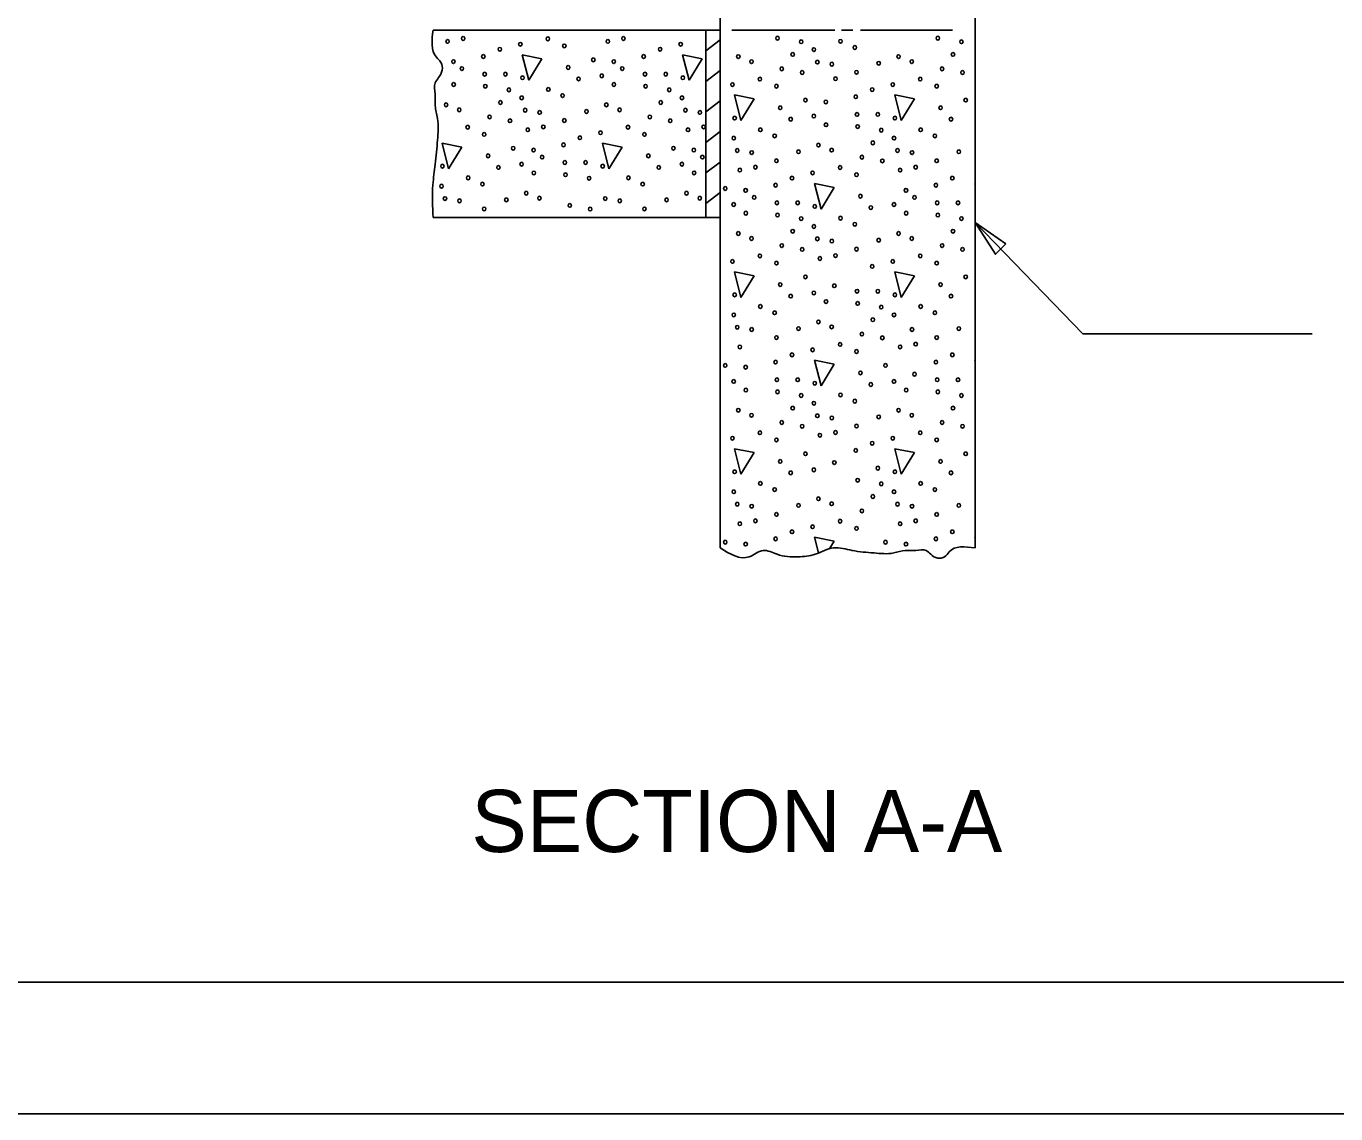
# Model space of a CAD drawing. Extents: x 0 to 34, y 0 to 22.
# Drawn here: x 9.28 to 14.256, y 0 to 4.131 of the extents above; entities that cross this region are included whole.
import ezdxf

# ---------------------------------------------------------------- set-up
doc = ezdxf.new("R2010")
doc.units = 0
for name, color, linetype in [('SH_Border', 7, 'Continuous'), ('SH_Cut_Line', 7, 'Continuous'), ('ST_Details', 7, 'Continuous'), ('ST_Text', 7, 'Continuous')]:
    doc.layers.add(name, color=color, linetype=linetype)

msp = doc.modelspace()

# ---------------------------------------------------------------- linework, layer by layer
at = {"layer": 'SH_Border'}
msp.add_lwpolyline([(2, 21.5), (33.5, 21.5), (33.5, 0.5), (2, 0.5)], close=True, dxfattribs=at)
at = {"layer": 'SH_Cut_Line'}
msp.add_lwpolyline([(0, 0), (34, 0), (34, 22), (0, 22)], close=True, dxfattribs=at)
at = {"layer": 'ST_Details'}
for p, q in [((12.8855, 2.1494), (12.8855, 5.9845)), ((11.9167, 4.294), (11.9167, 4.116)), ((11.8628, 4.116), (10.8265, 4.116)), ((11.9167, 4.116), (11.8628, 4.116)), ((11.8628, 4.1159), (11.8628, 3.4035)), ((11.9167, 3.3947), (11.9167, 4.116)), ((12.3533, 4.116), (11.962, 4.116)), ((12.4217, 4.116), (12.3782, 4.116)), ((12.8002, 4.116), (12.4497, 4.116)), ((11.1653, 4.0224), (11.1898, 3.925)), ((11.24, 4.0072), (11.1653, 4.0224)), ((11.1898, 3.925), (11.24, 4.0072)), ((11.7743, 4.0224), (11.799, 3.925)), ((11.8492, 4.0072), (11.7743, 4.0224)), ((11.799, 3.925), (11.8492, 4.0072)), ((11.9712, 3.8694), (11.9957, 3.772)), ((12.0458, 3.8542), (11.9712, 3.8694)), ((11.9957, 3.772), (12.0458, 3.8542)), ((12.5802, 3.8694), (12.6048, 3.772)), ((12.655, 3.8542), (12.5802, 3.8694)), ((12.6048, 3.772), (12.655, 3.8542)), ((10.8608, 3.6865), (10.8855, 3.5892)), ((11.4698, 3.6865), (11.4945, 3.5892)), ((11.5447, 3.6714), (11.4698, 3.6865)), ((10.8855, 3.5892), (10.9355, 3.6714)), ((11.4945, 3.5892), (11.5447, 3.6714)), ((12.2755, 3.5335), (12.3002, 3.4362)), ((12.3503, 3.5184), (12.2755, 3.5335)), ((12.3002, 3.4362), (12.3503, 3.5184)), ((10.8265, 3.4035), (11.8628, 3.4035)), ((11.8628, 3.4035), (11.9167, 3.4035)), ((11.9167, 3.3947), (11.9167, 2.1494)), ((11.9712, 3.1977), (11.9957, 3.1004)), ((12.0458, 3.1825), (11.9712, 3.1977)), ((12.5802, 3.1977), (12.6048, 3.1004)), ((12.655, 3.1825), (12.5802, 3.1977)), ((11.9957, 3.1004), (12.0458, 3.1825)), ((12.6048, 3.1004), (12.655, 3.1825)), ((12.2755, 2.8619), (12.3002, 2.7645)), ((12.3503, 2.8467), (12.2755, 2.8619)), ((12.3002, 2.7645), (12.3503, 2.8467)), ((11.9712, 2.526), (11.9957, 2.4287)), ((12.0458, 2.5109), (11.9712, 2.526)), ((11.9957, 2.4287), (12.0458, 2.5109)), ((12.5802, 2.526), (12.6048, 2.4287)), ((12.655, 2.5109), (12.5802, 2.526)), ((12.6048, 2.4287), (12.655, 2.5109)), ((12.2755, 2.1902), (12.2908, 2.1299)), ((12.3503, 2.175), (12.2755, 2.1902))]:
    msp.add_line(p, q, dxfattribs=at)
for points in [[(11.8627, 4.037), (11.9167, 4.0785)], [(11.8628, 3.921), (11.9165, 3.9625)], [(11.8628, 3.805), (11.9165, 3.8465)], [(10.9355, 3.6714), (10.8608, 3.6865)], [(11.8628, 3.6892), (11.9165, 3.7307)], [(11.8628, 3.5732), (11.9167, 3.6147)], [(12.8847, 3.5335), (12.8855, 3.5297)], [(12.8855, 3.5334), (12.8847, 3.5335)], [(11.8628, 3.4572), (11.9167, 3.4989)], [(12.8847, 2.8619), (12.8855, 2.858)], [(12.8855, 2.8617), (12.8847, 2.8619)], [(12.8847, 2.1902), (12.8855, 2.1865)], [(12.8855, 2.19), (12.8847, 2.1902)], [(12.3338, 2.1482), (12.3503, 2.175)]]:
    msp.add_lwpolyline(points, dxfattribs=at)
for centre in [(10.8814, 4.073), (10.9406, 4.084), (11.2624, 4.0827), (11.4904, 4.073), (11.5496, 4.084), (12.135, 4.0851), (12.3743, 4.0733), (12.7441, 4.0851), (11.0798, 4.0428), (11.158, 4.0618), (11.3249, 4.0555), (11.6889, 4.0428), (11.767, 4.0618), (12.1926, 4.0235), (12.2247, 4.0715), (12.2732, 4.0416), (12.4286, 4.0498), (12.8016, 4.0235), (12.8337, 4.0715), (10.9037, 3.996), (11.0174, 4.0156), (11.3397, 3.9739), (11.4351, 4.003), (11.5127, 3.996), (11.6264, 4.0156), (11.986, 4.015), (12.0361, 3.996), (12.2864, 3.9945), (12.3414, 3.9862), (12.5193, 3.9897), (12.595, 4.015), (12.6451, 3.996), (10.936, 3.9694), (11.0223, 3.9485), (11.1013, 3.9485), (11.1662, 3.9349), (11.3792, 3.9304), (11.4672, 3.9422), (11.545, 3.9694), (11.6314, 3.9485), (11.7103, 3.9485), (11.7752, 3.9349), (12.0681, 3.9298), (12.1512, 3.9688), (12.2288, 3.9546), (12.3554, 3.931), (12.4352, 3.9554), (12.6772, 3.9298), (12.7602, 3.9688), (12.8378, 3.9546), (10.9045, 3.9092), (11.0248, 3.9023), (11.1144, 3.8887), (11.2641, 3.8905), (11.5135, 3.9092), (11.6338, 3.9023), (11.7235, 3.8887), (11.9637, 3.9089), (12.1307, 3.9026), (12.4946, 3.8899), (12.5728, 3.9089), (12.7397, 3.9026), (10.8757, 3.8321), (11.0823, 3.8406), (11.1629, 3.8587), (11.3183, 3.8669), (11.4847, 3.8321), (11.6913, 3.8406), (11.7719, 3.8587), (12.2409, 3.85), (12.3185, 3.843), (12.4322, 3.8627), (12.8499, 3.85), (10.9258, 3.8131), (11.041, 3.7859), (11.1761, 3.8116), (11.2312, 3.8034), (11.4091, 3.8068), (11.5349, 3.8131), (11.65, 3.7859), (11.7851, 3.8116), (11.8402, 3.8034), (11.972, 3.7819), (12.1455, 3.821), (12.185, 3.7774), (12.2729, 3.7892), (12.4371, 3.7955), (12.5161, 3.7955), (12.581, 3.7819), (12.7545, 3.821), (12.794, 3.7774), (10.9579, 3.7469), (11.1185, 3.7717), (11.1859, 3.7372), (11.2451, 3.7481), (11.3249, 3.7725), (11.4625, 3.726), (11.5669, 3.7469), (11.7275, 3.7717), (11.7949, 3.7372), (11.8542, 3.7481), (12.0698, 3.7375), (12.3193, 3.7563), (12.4395, 3.7493), (12.5292, 3.7357), (12.6788, 3.7375), (11.0204, 3.7197), (11.3219, 3.6798), (11.3843, 3.707), (11.6294, 3.7197), (11.9687, 3.7058), (12.1241, 3.7139), (12.2905, 3.6792), (12.4971, 3.6876), (12.5777, 3.7058), (12.7331, 3.7139), (11.0352, 3.6381), (11.1306, 3.6671), (11.2082, 3.6601), (11.2405, 3.6336), (11.6442, 3.6381), (11.7396, 3.6671), (11.8172, 3.6601), (11.8495, 3.6336), (11.9819, 3.6586), (12.0369, 3.6504), (12.2148, 3.6538), (12.3406, 3.6602), (12.4557, 3.633), (12.5909, 3.6586), (12.646, 3.6504), (12.8238, 3.6538), (10.8617, 3.5991), (11.0747, 3.5945), (11.1627, 3.6064), (11.3268, 3.6127), (11.4058, 3.6127), (11.4707, 3.5991), (11.6837, 3.5945), (11.7717, 3.6064), (11.9917, 3.5843), (12.0509, 3.5952), (12.1307, 3.6196), (12.3727, 3.5939), (12.5333, 3.6187), (12.6007, 3.5843), (12.6599, 3.5952), (12.7397, 3.6196), (10.9595, 3.5546), (11.0138, 3.5311), (11.209, 3.5734), (11.3293, 3.5664), (11.419, 3.5528), (11.5686, 3.5546), (11.6228, 3.5311), (11.818, 3.5734), (12.1277, 3.5268), (12.1901, 3.554), (12.2683, 3.5731), (12.4352, 3.5667), (12.7367, 3.5268), (12.7991, 3.554), (10.8584, 3.5229), (11.1802, 3.4963), (11.2304, 3.4773), (11.7892, 3.4963), (11.8394, 3.4773), (11.9363, 3.5142), (12.0139, 3.5072), (12.0463, 3.4806), (12.45, 3.4851), (12.623, 3.5072), (12.6553, 3.4806), (10.8716, 3.4758), (10.9267, 3.4675), (11.0204, 3.4367), (11.1045, 3.471), (11.3455, 3.4501), (11.423, 3.4359), (11.4806, 3.4758), (11.5357, 3.4675), (11.6294, 3.4367), (11.7136, 3.471), (11.9684, 3.4534), (12.1326, 3.4597), (12.2116, 3.4597), (12.2765, 3.4461), (12.4895, 3.4416), (12.5774, 3.4534), (12.7416, 3.4597), (12.8206, 3.4597), (12.0147, 3.4204), (12.135, 3.4135), (12.2247, 3.3999), (12.3743, 3.4017), (12.4286, 3.3781), (12.6238, 3.4204), (12.7441, 3.4135), (12.8337, 3.3999), (11.986, 3.3434), (12.1926, 3.3518), (12.2732, 3.3699), (12.595, 3.3434), (12.8016, 3.3518), (12.0361, 3.3243), (12.1512, 3.2971), (12.2288, 3.2829), (12.2864, 3.3228), (12.3414, 3.3146), (12.4352, 3.2838), (12.5193, 3.318), (12.6451, 3.3243), (12.7602, 3.2971), (12.8378, 3.2829), (11.9637, 3.2372), (12.0681, 3.2581), (12.1307, 3.2309), (12.2962, 3.2484), (12.3554, 3.2593), (12.5728, 3.2372), (12.6772, 3.2581), (12.7397, 3.2309), (12.2409, 3.1784), (12.4946, 3.2182), (12.8499, 3.1784), (12.1455, 3.1493), (12.3508, 3.1448), (12.7545, 3.1493), (11.972, 3.1103), (12.185, 3.1058), (12.2729, 3.1176), (12.3193, 3.0846), (12.4371, 3.1239), (12.5161, 3.1239), (12.581, 3.1103), (12.794, 3.1058), (11.9687, 3.0341), (12.0698, 3.0659), (12.1241, 3.0423), (12.4395, 3.0777), (12.5292, 3.0641), (12.5777, 3.0341), (12.6788, 3.0659), (12.7331, 3.0423), (11.9819, 2.987), (12.0369, 2.9788), (12.2148, 2.9822), (12.2905, 3.0075), (12.3406, 2.9885), (12.4971, 3.016), (12.646, 2.9788), (12.8238, 2.9822), (12.1307, 2.9479), (12.4557, 2.9613), (12.5333, 2.9471), (12.7397, 2.9479), (11.9917, 2.9126), (12.1901, 2.8824), (12.2683, 2.9014), (12.3727, 2.9223), (12.4352, 2.8951), (12.6007, 2.9126), (12.6599, 2.9235), (12.7991, 2.8824), (11.9363, 2.8425), (12.0139, 2.8355), (12.1277, 2.8552), (12.5454, 2.8425), (12.7367, 2.8552), (11.9684, 2.7817), (12.1326, 2.7881), (12.2116, 2.7881), (12.45, 2.8135), (12.5774, 2.7817), (12.6553, 2.809), (12.7416, 2.7881), (12.8206, 2.7881), (12.0147, 2.7488), (12.135, 2.7418), (12.2765, 2.7745), (12.3743, 2.73), (12.4895, 2.7699), (12.6238, 2.7488), (12.7441, 2.7418), (12.1926, 2.6802), (12.2247, 2.7282), (12.2732, 2.6983), (12.4286, 2.7065), (12.8016, 2.6802), (12.8337, 2.7282), (11.986, 2.6717), (12.0361, 2.6527), (12.2864, 2.6512), (12.3414, 2.6429), (12.5193, 2.6464), (12.595, 2.6717), (12.6451, 2.6527), (12.0681, 2.5865), (12.1512, 2.6255), (12.2288, 2.6113), (12.3554, 2.5877), (12.4352, 2.6121), (12.6772, 2.5865), (12.7602, 2.6255), (12.8378, 2.6113), (11.9637, 2.5656), (12.1307, 2.5593), (12.2962, 2.5768), (12.4946, 2.5466), (12.5728, 2.5656), (12.7397, 2.5593), (12.2409, 2.5067), (12.4322, 2.5194), (12.8499, 2.5067), (11.972, 2.4386), (12.1455, 2.4777), (12.185, 2.4341), (12.2729, 2.4459), (12.3508, 2.4731), (12.5161, 2.4522), (12.581, 2.4386), (12.7545, 2.4777), (12.794, 2.4341), (12.0698, 2.3942), (12.4395, 2.406), (12.5292, 2.3924), (12.6788, 2.3942), (11.9687, 2.3625), (12.1241, 2.3706), (12.2905, 2.3359), (12.4971, 2.3443), (12.5777, 2.3625), (12.7331, 2.3706), (11.9819, 2.3153), (12.0369, 2.3071), (12.2148, 2.3105), (12.3406, 2.3169), (12.4557, 2.2897), (12.5909, 2.3153), (12.646, 2.3071), (12.8238, 2.3105), (11.9917, 2.241), (12.0509, 2.2519), (12.1307, 2.2763), (12.3727, 2.2506), (12.6007, 2.241), (12.6599, 2.2519), (12.7397, 2.2763), (12.1277, 2.1835), (12.1901, 2.2107), (12.2683, 2.2298), (12.4352, 2.2234), (12.7367, 2.1835), (12.7991, 2.2107), (11.9363, 2.1709), (12.0139, 2.1639), (12.5454, 2.1709), (12.623, 2.1639)]:
    msp.add_ellipse(centre, major_axis=(0, 0.00718), ratio=0.906762, dxfattribs=at)
for points in [[(10.8265, 4.116), (10.8388, 4.0127), (10.8563, 3.9932), (10.8608, 3.9642), (10.8475, 3.9352), (10.8345, 3.9157), (10.8345, 3.8722), (10.8345, 3.8287), (10.8432, 3.7802), (10.8432, 3.6979), (10.8345, 3.6059), (10.8255, 3.5284), (10.8265, 3.4035)], [(11.9167, 2.1494), (12.0277, 2.1154), (12.0805, 2.1395), (12.1332, 2.125), (12.2122, 2.1154), (12.278, 2.125), (12.3482, 2.1494), (12.4185, 2.1395), (12.5018, 2.1299), (12.5765, 2.1299), (12.6205, 2.1395), (12.66, 2.1395), (12.6995, 2.1395), (12.717, 2.125), (12.7435, 2.1105), (12.7698, 2.1154), (12.7873, 2.1347), (12.8855, 2.1494)]]:
    msp.add_spline(points, degree=3, dxfattribs=at)
at = {"layer": 'ST_Text'}
msp.add_lwpolyline([(12.8855, 3.3846), (13.2952, 2.9617), (14.1661, 2.9617)], dxfattribs=at)
msp.add_lwpolyline([(13.003, 3.3035), (12.9628, 3.2646), (12.8855, 3.3846)], close=True, dxfattribs=at)

# ---------------------------------------------------------------- texts
msp.add_text('SECTION A-A', height=0.2361, dxfattribs=at).set_placement((10.9717, 0.9942))

doc.saveas('drawing.dxf')
